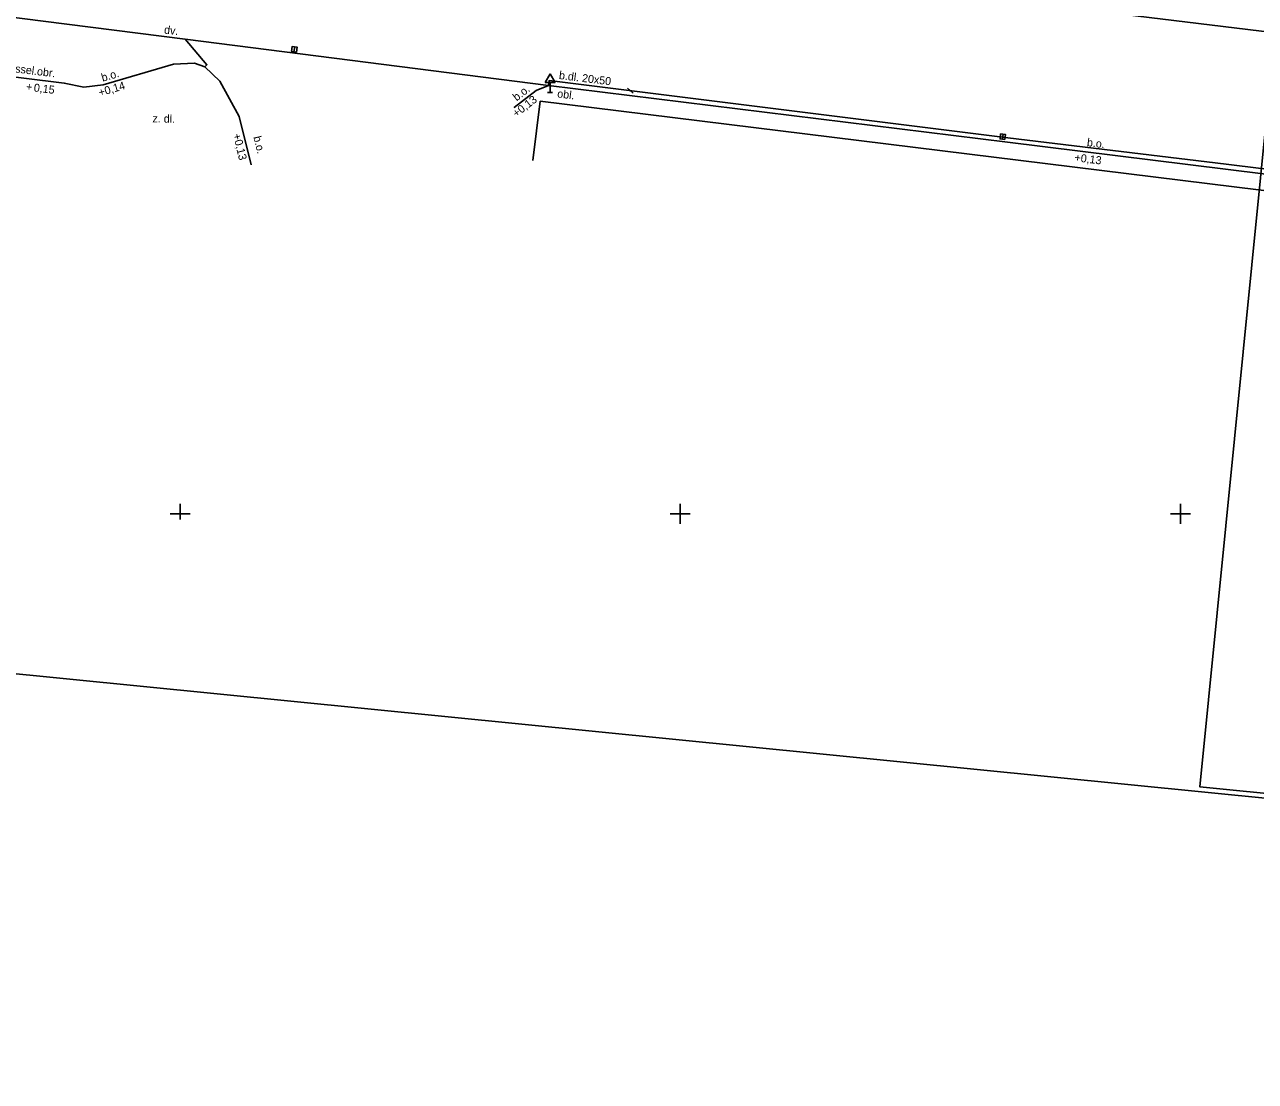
# Model space of a CAD drawing. Extents: x -598693 to -598360, y -1162453 to -1162007.
# Drawn here: x -598607.8 to -598546.3, y -1162453.4 to -1162400.5 of the extents above; entities that cross this region are included whole.
import ezdxf

# ---------------------------------------------------------------- set-up
doc = ezdxf.new("R2010")
doc.units = 0
for name, color, linetype in [('Vrstva 19', 7, 'Continuous'), ('Vrstva 2', 7, 'Continuous'), ('Vrstva 25', 7, 'Continuous'), ('Vrstva 4', 7, 'Continuous'), ('Vrstva 49', 7, 'Continuous'), ('Vrstva 50', 7, 'Continuous'), ('Vrstva 62', 7, 'Continuous'), ('Vrstva 63', 7, 'Continuous'), ('Vrstva 7', 7, 'Continuous')]:
    doc.layers.add(name, color=color, linetype=linetype)

msp = doc.modelspace()

# ---------------------------------------------------------------- linework, layer by layer
at = {"layer": 'Vrstva 19'}
for p, q in [((-598581.51, -1162403.007), (-598581.76, -1162403.44)), ((-598581.51, -1162403.007), (-598581.26, -1162403.44)), ((-598581.76, -1162403.44), (-598581.26, -1162403.44)), ((-598581.51, -1162403.94), (-598581.51, -1162403.44)), ((-598581.635, -1162403.94), (-598581.385, -1162403.94))]:
    msp.add_line(p, q, dxfattribs=at)
at = {"layer": 'Vrstva 2'}
for points in [[(-598692.873, -1162424.561), (-598651.24, -1162006.63), (-598503.471, -1162021.35), (-598545.104, -1162439.282)], [(-598692.873, -1162424.561), (-598651.24, -1162006.63), (-598503.471, -1162021.35), (-598545.104, -1162439.282)], [(-598507.399, -1162020.712), (-598549.031, -1162438.644), (-598401.263, -1162453.364), (-598359.63, -1162035.432)]]:
    msp.add_lwpolyline(points, close=True, dxfattribs=at)
at = {"layer": 'Vrstva 25'}
for p, q in [((-598594.309, -1162401.904), (-598594.271, -1162401.656)), ((-598558.894, -1162406.274), (-598558.866, -1162406.026))]:
    msp.add_line(p, q, dxfattribs=at)
for points in [[(-598594.185, -1162401.922), (-598594.148, -1162401.675), (-598594.395, -1162401.638), (-598594.432, -1162401.885)], [(-598558.77, -1162406.289), (-598558.741, -1162406.04), (-598558.99, -1162406.011), (-598559.019, -1162406.26)]]:
    msp.add_lwpolyline(points, close=True, dxfattribs=at)
at = {"layer": 'Vrstva 4'}
msp.add_line((-598582.376, -1162407.346), (-598582, -1162404.37), dxfattribs=at)
msp.add_lwpolyline([(-598489.95, -1162415.99), (-598489.96, -1162415.73), (-598582, -1162404.37)], dxfattribs=at)
at = {"layer": 'Vrstva 49'}
msp.add_line((-598577.36, -1162403.98), (-598577.63, -1162403.72), dxfattribs=at)
at = {"layer": 'Vrstva 62'}
for p, q in [((-598600, -1162425.282), (-598600, -1162424.5)), ((-598575, -1162425.5), (-598575, -1162424.5)), ((-598550, -1162425.5), (-598550, -1162424.5)), ((-598600.5, -1162425), (-598599.5, -1162425)), ((-598575.5, -1162425), (-598574.5, -1162425)), ((-598550.5, -1162425), (-598549.5, -1162425))]:
    msp.add_line(p, q, dxfattribs=at)
at = {"layer": 'Vrstva 63'}
msp.add_lwpolyline([(-598530.28, -1162409.94), (-598547.75, -1162407.77), (-598558.64, -1162406.42), (-598581.59, -1162403.59), (-598599.75, -1162401.27), (-598613.83, -1162399.49), (-598623.63, -1162398.36), (-598625.72, -1162398.27), (-598639.91, -1162396.97), (-598643.9, -1162396.57), (-598644.89, -1162396.45), (-598645.61, -1162396.69), (-598645.96, -1162397.37), (-598645.75, -1162390.37), (-598645.62, -1162385.09), (-598645.7, -1162378.05), (-598641.8, -1162378.3), (-598642.13, -1162376.31), (-598642.05, -1162373.23), (-598641.85, -1162368.87), (-598640.89, -1162354.82), (-598639.77, -1162342.39), (-598638.09, -1162327.94)], dxfattribs=at)
at = {"layer": 'Vrstva 7'}
for points in [[(-598632.99, -1162399.9), (-598631.14, -1162399.17), (-598628.58, -1162398.54), (-598625.72, -1162398.27), (-598623.63, -1162398.36), (-598613.83, -1162399.49), (-598599.75, -1162401.27), (-598598.66, -1162402.55), (-598598.76, -1162402.66)], [(-598555.26, -1162399.75), (-598537.32, -1162401.92)], [(-598622.81, -1162401.5), (-598621.8, -1162401.5), (-598605.79, -1162403.47), (-598604.81, -1162403.68)], [(-598604.81, -1162403.68), (-598603.85, -1162403.56), (-598600.33, -1162402.53), (-598599.28, -1162402.48), (-598598.76, -1162402.66), (-598598.01, -1162403.37), (-598597.04, -1162405.14), (-598596.44, -1162407.56)], [(-598479.25, -1162426.76), (-598479.18, -1162423.74), (-598479.96, -1162420.81), (-598481.63, -1162418.26), (-598483.16, -1162416.91), (-598484.89, -1162415.93), (-598487.27, -1162415.22), (-598488.68, -1162415.05), (-598503.03, -1162413.27), (-598517.53, -1162411.52), (-598530.28, -1162409.94), (-598547.75, -1162407.77), (-598558.64, -1162406.42), (-598581.59, -1162403.59), (-598582.21, -1162403.84), (-598583.3, -1162404.69), (-598583.28, -1162404.68)], [(-598488.68, -1162415.05), (-598488.65, -1162414.79), (-598503.01, -1162413.03), (-598517.53, -1162411.29), (-598530.23, -1162409.68), (-598547.71, -1162407.53), (-598558.63, -1162406.21), (-598581.55, -1162403.34), (-598581.55, -1162403.35), (-598581.59, -1162403.59)]]:
    msp.add_lwpolyline(points, dxfattribs=at)

# ---------------------------------------------------------------- texts
at = {"layer": 'Vrstva 49'}
for s, rotation, p in [('dv.', 352.79486, (-598600.816, -1162400.987)), ('kassel.obr.', 352.98513, (-598608.82, -1162402.866)), ('b.o.', 16.3102, (-598603.868, -1162403.404)), ('b.dl. 20x50', 352.97026, (-598581.079, -1162403.265)), ('b.o.', 37.94769, (-598583.177, -1162404.392)), ('obl.', 352.96388, (-598581.165, -1162404.182)), ('z. dl.', 358.69517, (-598601.383, -1162405.432)), ('b.o.', 283.92477, (-598596.342, -1162406.168)), ('b.o.', 352.93327, (-598554.691, -1162406.618))]:
    msp.add_text(s, height=0.4, rotation=rotation, dxfattribs=at).set_placement(p)
at = {"layer": 'Vrstva 50'}
for s, rotation, p in [('+', 352.98513, (-598607.718, -1162403.837)), ('0,15', 352.98513, (-598607.327, -1162403.885)), ('+0,14', 16.3102, (-598604.011, -1162404.144)), ('+0,13', 37.94769, (-598583.188, -1162405.2)), ('+0,13', 283.92477, (-598597.365, -1162406.043)), ('+0,13', 352.93327, (-598555.313, -1162407.374))]:
    msp.add_text(s, height=0.4, rotation=rotation, dxfattribs=at).set_placement(p)

doc.saveas('drawing.dxf')
